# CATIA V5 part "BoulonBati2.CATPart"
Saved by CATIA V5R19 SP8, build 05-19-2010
Part number: BoulonBati2
Bounding box of the stored display mesh (mm): x -38 to 34, y 2 to 18, z 612 to 628
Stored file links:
  G:\EU_thinkMotion\CFAO_2010\MMS_groupe3\MMS_groupe3\A reprendre\fovide\fovide\BoulonBati2.CATPart
  C:\Users\Rodger\Desktop\Part11.CATPart
  G:\EU_thinkMotion\CFAO_2010\MMS_groupe3\MMS_groupe3\A reprendre\fovide\fovide\fovide.CATProduct
  G:\EU_thinkMotion\CFAO_2010\MMS_groupe3\MMS_groupe3\A reprendre\fovide\fovide\Bati.CATPart
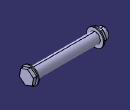
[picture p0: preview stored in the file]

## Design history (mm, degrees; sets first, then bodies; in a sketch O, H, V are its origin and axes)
Parameters
  Diametre = 10 mm
  Longueur = 60 mm
Set1
  DatumSurface1: linked copy from another document
  Point1: linked copy from another document
Body1 (main body)
Body2
  Sketch1 on DatumSurface1, origin (30, 0, 30), H (0, 0, -1), V (0, 1, 0)
    circle A1 centre (-590, 10) radius 8
    point P1 (-590, 10)
    reference projected point E1 (-590, 10) from Point1
    radius A1 = 8 {= Diametre *8/10}
    coincidence: P1 E1
  Pad1: profile Sketch1, direction (1, 0, 0), length 1
  Sketch2 on end face of Pad1, origin (31, 0, 32), H (0, 0, -1), V (0, 1, 0)
    point P1 (-588, 10)
    point P2 (-585.5061, 3.4593)
    point P3 (-581.0887, 8.8894)
    point P4 (-583.5825, 15.4301)
    point P5 (-590.4939, 16.5407)
    point P6 (-594.9113, 11.1106)
    point P7 (-592.4175, 4.5699)
    point P8 (-583.2974, 6.1744)
    line L1 (-585.5061, 3.4593) -> (-581.0887, 8.8894)
    line L2 (-581.0887, 8.8894) -> (-583.5825, 15.4301)
    line L3 (-583.5825, 15.4301) -> (-590.4939, 16.5407)
    line L4 (-590.4939, 16.5407) -> (-594.9113, 11.1106)
    line L5 (-594.9113, 11.1106) -> (-592.4175, 4.5699)
    line L6 (-592.4175, 4.5699) -> (-585.5061, 3.4593)
    construction line L7 (-588, 10) -> (-583.2974, 6.1744)
    construction circle A1 centre (-588, 10) radius 7
    construction arc A2 centre (-594.9113, 11.1106) radius 7 from (-590.4939, 16.5407) to (-592.4175, 4.5699) cw
    construction arc A3 centre (-581.0887, 8.8894) radius 7 from (-583.5825, 15.4301) to (-585.5061, 3.4593) ccw
    reference projected point E1 (-588, 10) from Point1
    radius A1 = 7 {= Diametre *7/10}
    coincidence: A1 P2, A1 P3, A1 P4, A1 P5, A1 P6, A1 P7, A2 P1, A3 P1, P1 E1
    midpoint: P8 L1
    parallelism: L1 L4
  Pad2: profile Sketch2, direction (1, 0, 0), length 3
  Sketch3 on start face of Pad1, origin (30, 0, 30), H (0, 0, -1), V (0, -1, 0)
    circle A1 centre (-590, -10) radius 5
    point P1 (-590, -10)
    reference projected point E1 (-590, -10) from Point1
    radius A1 = 5 {= Diametre /2}
    coincidence: P1 E1
  Pad3: profile Sketch3, direction (-1, 0, 0), length 60 {= Longueur}
  Sketch4 on end face of Pad3, origin (-30, 0, -50), H (0, 0, -1), V (0, -1, 0)
    circle A1 centre (-670, -10) radius 8
    point P1 (-670, -10)
    reference projected point E1 (-670, -10) from Point1
    radius A1 = 8 {= Diametre *8/10}
    coincidence: P1 E1
  Pad4: profile Sketch4, direction (-1, 0, 0), length 1
  Sketch5 on end face of Pad4, origin (-31, 0, -52), H (0, 0, -1), V (0, -1, 0)
    point P1 (-672, -10)
    point P2 (-672.0478, -16.9998)
    point P3 (-665.9619, -13.5413)
    point P4 (-665.9141, -6.5415)
    point P5 (-671.9522, -3.0002)
    point P6 (-678.0381, -6.4587)
    point P7 (-678.0859, -13.4585)
    point P8 (-669.0048, -15.2706)
    line L1 (-672.0478, -16.9998) -> (-665.9619, -13.5413)
    line L2 (-665.9619, -13.5413) -> (-665.9141, -6.5415)
    line L3 (-665.9141, -6.5415) -> (-671.9522, -3.0002)
    line L4 (-671.9522, -3.0002) -> (-678.0381, -6.4587)
    line L5 (-678.0381, -6.4587) -> (-678.0859, -13.4585)
    line L6 (-678.0859, -13.4585) -> (-672.0478, -16.9998)
    construction line L7 (-672, -10) -> (-669.0048, -15.2706)
    construction circle A1 centre (-672, -10) radius 7
    construction arc A2 centre (-678.0381, -6.4587) radius 7 from (-671.9522, -3.0002) to (-678.0859, -13.4585) cw
    construction arc A3 centre (-665.9619, -13.5413) radius 7 from (-665.9141, -6.5415) to (-672.0478, -16.9998) ccw
    reference projected point E1 (-672, -10) from Point1
    radius A1 = 7 {= Diametre *7/10}
    coincidence: A1 P2, A1 P3, A1 P4, A1 P5, A1 P6, A1 P7, A2 P1, A3 P1, P1 E1
    midpoint: P8 L1
    parallelism: L1 L4
  Pad5: profile Sketch5, direction (-1, 0, 0), length 3
  Sketch6 on end face of Pad5, origin (-34, 0, -58), H (0, 0, -1), V (0, -1, 0)
    circle A1 centre (-678, -10) radius 5
    point P1 (-678, -10)
    reference projected point E1 (-678, -10) from Point1
    radius A1 = 5 {= Diametre /2}
    coincidence: P1 E1
  Pad6: profile Sketch6, direction (-1, 0, 0), length 4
